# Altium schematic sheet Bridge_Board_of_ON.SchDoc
size A3
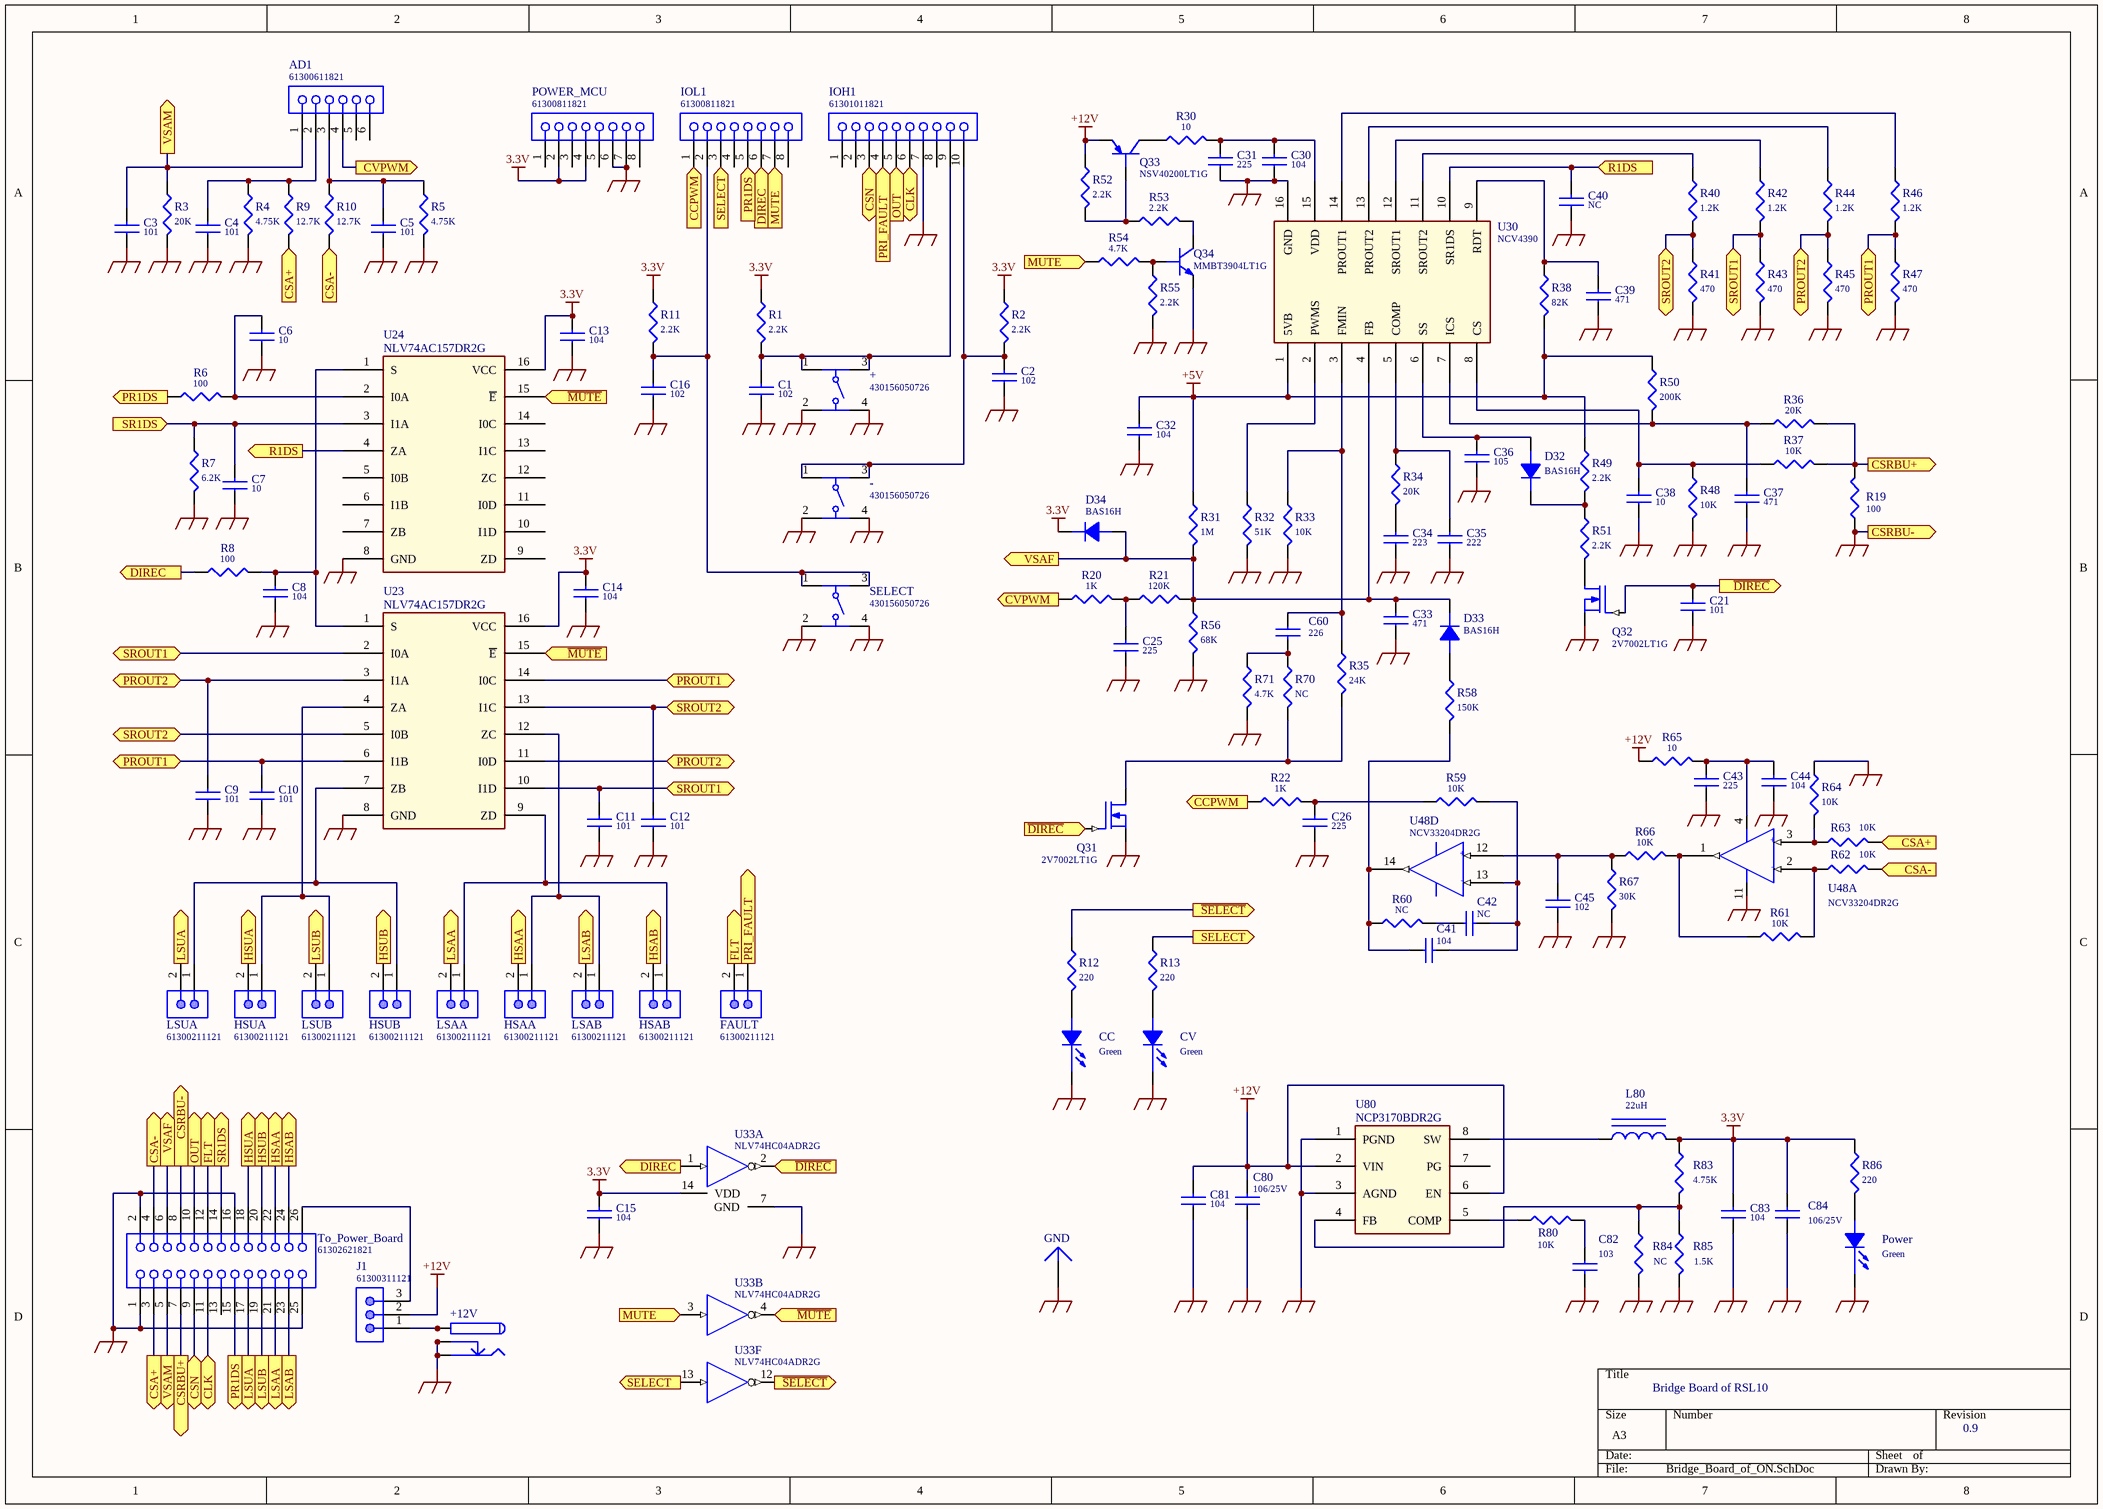
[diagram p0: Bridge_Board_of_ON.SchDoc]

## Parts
+  430156050726  [4301x60507x6]
+12V  PWR2.5  [KLD-0202]  (value not drawn)
-  430156050726  [4301x60507x6]
AD1  61300611821  [61300611821]
C1  102  [SMT_0805_CM]
C2  102  [SMT_0805_CM]
C3  101  [SMT_0805_CM]
C4  101  [SMT_0805_CM]
C5  101  [SMT_0805_CM]
C6  10  [SMT_0805_CM]
C7  10  [SMT_0805_CM]
C8  104  [SMT_0805_CM]
C9  101  [SMT_0805_CM]
C10  101  [SMT_0805_CM]
C11  101  [SMT_0805_CM]
C12  101  [SMT_0805_CM]
C13  104  [SMT_0805_CM]
C14  104  [SMT_0805_CM]
C15  104  [SMT_0805_CM]
C16  102  [SMT_0805_CM]
C21  101  [SMT_0805_CM]
C25  225  [SMT_0805_CM]
C26  225  [SMT_0805_CM]
C30  104  [SMT_0805_CM]
C31  225  [SMT_0805_CM]
C32  104  [SMT_0805_CM]
C33  471  [SMT_0805_CM]
C34  223  [SMT_0805_CM]
C35  222  [SMT_0805_CM]
C36  105  [SMT_0805_CM]
C37  471  [SMT_0805_CM]
C38  10  [SMT_0805_CM]
C39  471  [SMT_0805_CM]
C40  NC  [SMT_0805_CM]
C41  104  [SMT_0805_CM]
C42  NC  [SMT_0805_CM]
C43  225  [SMT_0805_CM]
C44  104  [SMT_0805_CM]
C45  102  [SMT_0805_CM]
C60  226  [SMT_1210]
C80  106/25V  [SMT_1206_CM]
C81  104  [SMT_0805_CM]
C82  103  [SMT_0805_CM]
C83  104  [SMT_0805_CM]
C84  106/25V  [SMT_1206_CM]
CC  Green  [LED 5MM-R]
CV  Green  [LED 5MM-R]
D32  BAS16H  [SOD-323M]
D33  BAS16H  [SOD-323M]
D34  BAS16H  [SOD-323M]
FAULT  61300211121  [61300211121]
GND  (no value)  [test]
HSAA  61300211121  [61300211121]
HSAB  61300211121  [61300211121]
HSUA  61300211121  [61300211121]
HSUB  61300211121  [61300211121]
IOH1  61301011821  [61301011821]
IOL1  61300811821  [61300811821]
J1  61300311121  [61300311121]
L80  22uH  [INDUCTOR-7*7*3.5]
LSAA  61300211121  [61300211121]
LSAB  61300211121  [61300211121]
LSUA  61300211121  [61300211121]
LSUB  61300211121  [61300211121]
Power  Green  [LED 5MM-R]
POWER_MCU  61300811821  [61300811821]
Q31  2V7002LT1G  [SOT-23-3L]
Q32  2V7002LT1G  [SOT-23-3L]
Q33  NSV40200LT1G  [SOT-23-3L]
Q34  MMBT3904LT1G  [SOT-23-3L]
R1  2.2K  [SMT_0805_RM]
R2  2.2K  [SMT_0805_RM]
R3  20K  [SMT_0805_RM]
R4  4.75K  [SMT_0805_RM]
R5  4.75K  [SMT_0805_RM]
R6  100  [SMT_0805_RM]
R7  6.2K  [SMT_0805_RM]
R8  100  [SMT_0805_RM]
R9  12.7K  [SMT_0805_RM]
R10  12.7K  [SMT_0805_RM]
R11  2.2K  [SMT_0805_RM]
R12  220  [SMT_0805_RM]
R13  220  [SMT_0805_RM]
R19  100  [SMT_1206_RM]
R20  1K  [SMT_0805_RM]
R21  120K  [SMT_0805_RM]
R22  1K  [SMT_0805_RM]
R30  10  [SMT_0805_RM]
R31  1M  [SMT_0805_RM]
R32  51K  [SMT_0805_RM]
R33  10K  [SMT_0805_RM]
R34  20K  [SMT_0805_RM]
R35  24K  [SMT_0805_RM]
R36  20K  [SMT_0805_RM]
R37  10K  [SMT_0805_RM]
R38  82K  [SMT_0805_RM]
R40  1.2K  [SMT_0805_RM]
R41  470  [SMT_0805_RM]
R42  1.2K  [SMT_0805_RM]
R43  470  [SMT_0805_RM]
R44  1.2K  [SMT_0805_RM]
R45  470  [SMT_0805_RM]
R46  1.2K  [SMT_0805_RM]
R47  470  [SMT_0805_RM]
R48  10K  [SMT_0805_RM]
R49  2.2K  [SMT_0805_RM]
R50  200K  [SMT_0805_RM]
R51  2.2K  [SMT_0805_RM]
R52  2.2K  [SMT_0805_RM]
R53  2.2K  [SMT_0805_RM]
R54  4.7K  [SMT_0805_RM]
R55  2.2K  [SMT_0805_RM]
R56  68K  [SMT_0805_RM]
R58  150K  [SMT_0805_RM]
R59  10K  [SMT_0805_RM]
R60  NC  [SMT_0805_RM]
R61  10K  [SMT_0805_RM]
R62  10K  [SMT_0805_RM]
R63  10K  [SMT_0805_RM]
R64  10K  [SMT_0805_RM]
R65  10  [SMT_0805_RM]
R66  10K  [SMT_0805_RM]
R67  30K  [SMT_0805_RM]
R70  NC  [SMT_0805_RM]
R71  4.7K  [SMT_0805_RM]
R80  10K  [SMT_0805_RM]
R83  4.75K  [SMT_0805_RM]
R84  NC  [SMT_0805_RM]
R85  1.5K  [SMT_0805_RM]
R86  220  [SMT_0805_RM]
SELECT  430156050726  [4301x60507x6]
To_Power_Board  61302621821  [61302621821]
U23  NLV74AC157DR2G  [SOP16]
U24  NLV74AC157DR2G  [SOP16]
U30  NCV4390  [SOP16_NW]
U33  NLV74HC04ADR2G  [751A-03_N]  (parts A,B,F of 6)
U48  NCV33204DR2G  [SOP14]  (parts A,D of 4)
U80  NCP3170BDR2G  [Sop8]

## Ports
CCPWM (out), CLK, CSA+ (out), CSA- (out), CSN, CSRBU+ (out), CSRBU- (out), CVPWM (out), DIREC (out), FLT (out), HSAA (out), HSAB (out), HSUA (out), HSUB (out), LSAA (out), LSAB (out), LSUA (out), LSUB (out), MUTE (out), OUT (out), PR1DS (in), PR1DS (out), PRI_FAULT (out), PROUT1, PROUT2, R1DS (in), R1DS (out), SELECT (out), SR1DS (in), SR1DS (out), SROUT1, SROUT2, VSAF (out), VSAM (out), ~{DIREC} (out), ~{MUTE} (out), ~{SELECT} (out)

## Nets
3.3V: C13.2 C14.2 C15.2 C83.2 C84.2 D34.2(K) L80.2 POWER_MCU.2 POWER_MCU.4 R1.1 R2.1 R11.1 R83.1 R86.1 U23.16(VCC) U24.16(VCC) U33.14(VDD)
+5V: C32.2 R31.1 R38.2 R49.1 R50.1 U30.1(5VB)
+12V: C80.2 C81.2 J1.2 Q33.2(E) R52.1 R65.1 U80.2(VIN) U80.6(EN)
GND: +.2 +.4 +12V.2 +12V.2A +12V.2B +12V.3 +12V.3A +12V.3B -.2 -.4 C1.1 C2.1 C3.1 C4.1 C5.1 C6.1 C7.1 C8.1 C9.1 C10.1 C11.1 C12.1 C13.1 C14.1 C15.1 C16.1 C21.1 C25.1 C26.1 C30.1 C31.1 C32.1 C33.1 C34.1 C35.1 C36.1 C37.1 C38.1 C39.1 C40.1 C43.1 C44.1 C45.1 C80.1 C81.1 C82.2 C83.1 C84.1 CC.2(CATHODE) CV.2(CATHODE) GND.1 IOH1.7 Power.2(CATHODE) POWER_MCU.6 POWER_MCU.7 Q31.2(SOURCE) Q32.2(SOURCE) Q34.2(E) R3.2 R4.2 R5.2 R7.2 R19.1 R32.2 R33.2 R41.2 R43.2 R45.2 R47.2 R48.2 R55.2 R56.2 R64.1 R67.2 R71.2 R84.2 R85.2 SELECT.2 SELECT.4 To_Power_Board.1 To_Power_Board.2 To_Power_Board.8 To_Power_Board.16 To_Power_Board.25 U23.8(GND) U24.8(GND) U30.16(GND) U33.7(GND) U48.11(Vee) U80.1(PGND) U80.3(AGND) ; port CSRBU-
VDD: U33.14(VDD)
CCPWM: IOL1.1 R22.1 ; port CCPWM
CLK: IOH1.6 To_Power_Board.11 ; port CLK
CSA+: R9.2 R63.2 To_Power_Board.3 ; port CSA+
CSA-: R10.2 R62.2 To_Power_Board.4 ; port CSA-
CSN: IOH1.3 To_Power_Board.9 ; port CSN
CSRBU+: R19.2 R36.2 R37.2 To_Power_Board.7 ; port CSRBU+
CVPWM: AD1.4 R20.1 ; port CVPWM
~{DIREC}: C21.2 Q31.1(GATE) Q32.1(GATE) U33.2(~{OUT}) ; port ~{DIREC}
DIREC: IOL1.6 R8.1 U33.1(IN) ; port DIREC
FLT: FAULT.2 To_Power_Board.12 ; port FLT
HSAA: HSAA.2 To_Power_Board.22 ; port HSAA
HSAB: HSAB.2 To_Power_Board.24 ; port HSAB
HSUA: HSUA.2 To_Power_Board.18 ; port HSUA
HSUB: HSUB.2 To_Power_Board.20 ; port HSUB
LSAA: LSAA.2 To_Power_Board.21 ; port LSAA
LSAB: LSAB.2 To_Power_Board.23 ; port LSAB
LSUA: LSUA.2 To_Power_Board.17 ; port LSUA
LSUB: LSUB.2 To_Power_Board.19 ; port LSUB
~{MUTE}: U23.15(~{E}) U24.15(~{E}) U33.4(~{OUT}) ; port ~{MUTE}
MUTE: IOL1.7 R54.1 U33.3(IN) ; port MUTE
OUT: IOH1.5 To_Power_Board.10 ; port OUT
PR1DS: IOL1.5 R6.1 To_Power_Board.15 ; port PR1DS
PRI_FAULT: FAULT.1 IOH1.4 ; port PRI_FAULT
PROUT1: C10.2 R46.2 R47.1 U23.6(I1B) U23.14(I0C) ; port PROUT1
PROUT2: C9.2 R44.2 R45.1 U23.3(I1A) U23.11(I0D) ; port PROUT2
R1DS: C40.2 U24.4(ZA) U30.10(SR1DS) ; port R1DS
~{SELECT}: R12.1 U33.12(~{OUT}) ; port ~{SELECT}
SELECT: IOL1.3 R13.1 U33.13(IN) ; port SELECT
SR1DS: C7.2 R7.1 To_Power_Board.14 U24.3(I1A) ; port SR1DS
SROUT1: C11.2 R42.2 R43.1 U23.2(I0A) U23.10(I1D) ; port SROUT1
SROUT2: C12.2 R40.2 R41.1 U23.5(I0B) U23.13(I1C) ; port SROUT2
VSAF: C33.2 D33.2(K) D34.1(A) R21.2 R31.2 R56.1 To_Power_Board.6 U30.4(FB) ; port VSAF
VSAM: AD1.1 C3.2 R3.1 To_Power_Board.5 ; port VSAM
Net+12V_1: +12V.1 +12V.1A +12V.1B J1.1
Net+_1: +.1 +.3 C1.2 IOH1.9 R1.2
Net-_1: -.1 -.3 C2.2 IOH1.10 R2.2
NetAD1_2: AD1.2 C4.2 R4.1 R9.1
NetAD1_3: AD1.3 C5.2 R5.1 R10.1
NetC6_2: C6.2 R6.2 U24.2(I0A)
NetC8_2: C8.2 R8.2 U23.1(S) U24.1(S)
NetC16_2: C16.2 IOL1.2 R11.2 SELECT.1 SELECT.3
NetC25_2: C25.2 R20.2 R21.1
NetC26_2: C26.2 R22.2 R59.1
NetC30_2: C30.2 C31.2 R30.2 U30.15(VDD)
NetC34_2: C34.2 R34.2
NetC35_2: C35.2 R34.1 U30.5(COMP)
NetC36_2: C36.2 D32.1(A) U30.6(SS)
NetC37_2: C37.2 R36.1 R50.2 U30.7(ICS)
NetC38_2: C38.2 R37.1 R48.1 U30.8(CS)
NetC39_2: C39.2 R38.1 U30.9(RDT)
NetC41_1: C41.1 R58.2 R60.1 U48.14(OUT)
NetC41_2: C41.2 C42.2 R59.2 U48.13(-IN)
NetC42_1: C42.1 R60.2
NetC43_2: C43.2 C44.2 R65.2 U48.4(VCC)
NetC45_2: C45.2 R66.1 R67.1 U48.12(+IN)
NetC60_1: C60.1 R33.1 R35.1 U30.3(FMIN)
NetC60_2: C60.2 R70.1 R71.1
NetC82_1: C82.1 R80.2
NetCC_1: CC.1(ANODE) R12.2
NetCV_1: CV.1(ANODE) R13.2
NetD32_2: D32.2(K) R49.2 R51.1
NetD33_1: D33.1(A) R58.1
NetHSAA_1: HSAA.1 LSAB.1 U23.12(ZC)
NetHSAB_1: HSAB.1 LSAA.1 U23.9(ZD)
NetHSUA_1: HSUA.1 LSUB.1 U23.4(ZA)
NetHSUB_1: HSUB.1 LSUA.1 U23.7(ZB)
NetJ1_3: J1.3 To_Power_Board.26
NetL80_1: L80.1 U80.8(SW)
NetPower_1: Power.1(ANODE) R86.2
NetQ31_3: Q31.3(DRAIN) R35.2 R70.2
NetQ32_3: Q32.3(DRAIN) R51.2
NetQ33_1: Q33.1(B) R52.2 R53.1
NetQ33_3: Q33.3(C) R30.1
NetQ34_1: Q34.1(B) R54.2 R55.1
NetQ34_3: Q34.3(C) R53.2
NetR32_1: R32.1 U30.2(PWMS)
NetR40_1: R40.1 U30.11(SROUT2)
NetR42_1: R42.1 U30.12(SROUT1)
NetR44_1: R44.1 U30.13(PROUT2)
NetR46_1: R46.1 U30.14(PROUT1)
NetR61_1: R61.1 R66.2 U48.1(OUT)
NetR61_2: R61.2 R62.1 U48.2(-IN)
NetR63_1: R63.1 R64.2 U48.3(+IN)
NetR80_1: R80.1 U80.5(COMP)
NetR83_2: R83.2 R84.1 R85.1 U80.4(FB)

Not connected (* = marked no-connect by the designer): AD1 5 6; IOH1 1 2 8; IOL1 4 8; POWER_MCU 1 3 5 8; To_Power_Board 13; U24 5(I0B) 6(I1B) 7(ZB) 9(ZD) 10(I1D) 11(I0D) 12(ZC) 13(I1C) 14(I0C); U80 7(PG)

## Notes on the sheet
- Bridge Board of RSL10
- 0.9

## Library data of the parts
+ - SELECT = 430156050726: WS-TATV THT Tact Switch 6x6mm, height 5mm, 260gf; Rated Voltage: 12VDC; Rated Current: 50mA; Washable: No
+12V = PWR2.5: Low Voltage Power Supply Connector
AD1 = 61300611821: WR-PHD Socket Header, THT, pitch 2.54mm, Single Row, Vertical, 6pin; Pin Number: 6; Gender: Female; Rated Current: 3A; Working Voltage: 250VAC; Withstanding Voltage: 500VAC; Contact Resistance: 20mOhm
C1-C16 C21 C25 C26 C30-C40 C43-C45 C81 C83 = CAP_0805
C41 C42 C60 C80 C82 C84 = CAP NP
CC CV Power = LED
D32-D34 = DIODE
FAULT HSAA HSAB HSUA HSUB LSAA LSAB LSUA LSUB = 61300211121: WR-PHD Pin Header, THT, pitch 2.54mm, Single Row, Vertical, 2pin; Pin Number: 2; Gender: Male; Rated Current: 3A; Working Voltage: 250VAC; Withstanding Voltage: 500VAC; Contact Resistance: 20mOhm
GND = Plug
IOH1 = 61301011821: WR-PHD Socket Header, THT, pitch 2.54mm, Single Row, Vertical, 10pin; Pin Number: 10; Gender: Female; Rated Current: 3A; Working Voltage: 250VAC; Withstanding Voltage: 500VAC; Contact Resistance: 20mOhm
IOL1 POWER_MCU = 61300811821: WR-PHD Socket Header, THT, pitch 2.54mm, Single Row, Vertical, 8pin; Pin Number: 8; Gender: Female; Rated Current: 3A; Working Voltage: 250VAC; Withstanding Voltage: 500VAC; Contact Resistance: 20mOhm
J1 = 61300311121: WR-PHD Pin Header, THT, pitch 2.54mm, Single Row, Vertical, 3pin; Pin Number: 3; Gender: Male; Rated Current: 3A; Working Voltage: 250VAC; Withstanding Voltage: 500VAC; Contact Resistance: 20mOhm
L80 = INDUCTOR IRON
Q31 Q32 = MOSFET N: NTPF082N65S3F; R187: C158
Q33 = PNP BCE
Q34 = NPN BCE
R1-R5 R7 R9-R13 R19 R31-R35 R38 R40-R52 R55 R56 R58 R64 R67 R70 R71 R80 R83-R86 = R
R6 R8 R20-R22 R30 R36 R37 R53 R54 R59-R63 R65 R66 = R_0805
To_Power_Board = 61302621821: WR-PHD Socket Header, THT, pitch 2.54mm, Dual Row, Vertical, 26pin; Pin Number: 26; Gender: Female; Rated Current: 3A; Working Voltage: 250VAC; Withstanding Voltage: 500VAC; Contact Resistance: 20mOhm
U23 U24 = 74HC157
U30 = FAN7688
U33 = MC74HC04ADR2: Hex Inverter
U48 = LM324
U80 = NCP3170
